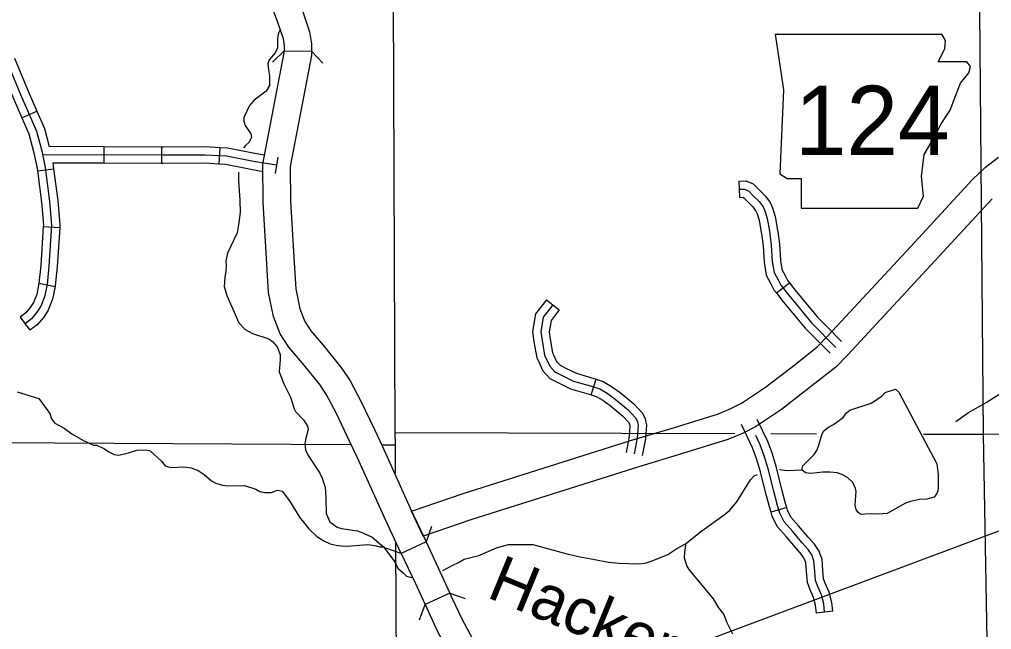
# Model space of a CAD drawing. Extents: x 1373862 to 1376999, y 1168398 to 1170455.
# Drawn here: x 1374862.3 to 1375039.9, y 1168964.7 to 1169076.3 of the extents above; entities that cross this region are included whole.
import ezdxf

# ---------------------------------------------------------------- set-up
doc = ezdxf.new("R2010")
doc.units = 0
for name, color, linetype in [('Level 10', 7, 'Continuous'), ('Level 21', 7, 'Continuous'), ('Level 32', 7, 'Continuous'), ('Level 35', 7, 'Continuous'), ('Level 37', 7, 'Continuous'), ('Level 4', 7, 'Continuous'), ('Level 45', 7, 'Continuous'), ('Level 5', 7, 'Continuous'), ('R_Draft', 7, 'Continuous')]:
    doc.layers.add(name, color=color, linetype=linetype)

msp = doc.modelspace()

# ---------------------------------------------------------------- linework, layer by layer
at = {"layer": 'Level 10'}
for p, q in [((1374910.63, 1169070.56), (1374915.63, 1169070.48)), ((1374936.55, 1168980.77), (1374932.03, 1168978.64)), ((1374940.91, 1168971.43), (1374936.37, 1168969.34))]:
    msp.add_line(p, q, dxfattribs=at)
for points in [[(1374912.68, 1169081.32), (1374914.09, 1169077.49), (1374915.29, 1169074.03), (1374915.65, 1169071.86), (1374915.63, 1169070.48)], [(1374907.99, 1169079.58), (1374909.39, 1169075.8), (1374910.43, 1169072.79), (1374910.65, 1169071.49), (1374910.63, 1169070.56)], [(1374932.03, 1168978.64), (1374929.18, 1168984.7), (1374924.04, 1168996.12), (1374922.59, 1168999.18), (1374920.12, 1169004.39), (1374918.39, 1169007.66), (1374917.16, 1169009.53), (1374913.92, 1169013.53), (1374911.5, 1169016.36), (1374909.93, 1169018.81), (1374908.7, 1169021.97), (1374907.79, 1169026.38), (1374907.46, 1169031.55), (1374906.79, 1169042.88), (1374906.71, 1169049.86), (1374910.63, 1169070.2), (1374910.63, 1169070.56)], [(1374915.63, 1169070.48), (1374915.62, 1169069.69), (1374911.71, 1169049.41), (1374911.79, 1169043.06), (1374912.46, 1169031.86), (1374912.76, 1169027.05), (1374913.51, 1169023.39), (1374914.41, 1169021.09), (1374915.53, 1169019.35), (1374917.77, 1169016.73), (1374921.19, 1169012.49), (1374922.7, 1169010.22), (1374924.59, 1169006.63), (1374927.11, 1169001.32), (1374928.58, 1168998.22), (1374933.72, 1168986.79), (1374936.55, 1168980.77)], [(1374936.04, 1168981.85), (1374933.89, 1168986.39), (1374943.36, 1168989.64), (1374973.92, 1168999.29), (1374981.94, 1169001.71), (1374989.99, 1169004.22), (1374992.37, 1169005.2), (1374994.19, 1169006.14), (1374998.57, 1169009.06), (1375003.98, 1169013.22), (1375008.03, 1169016.43), (1375009.97, 1169018.43), (1375025.11, 1169034.78), (1375036.38, 1169047.03), (1375038.77, 1169049.32), (1375041.11, 1169051.12)], [(1375039.95, 1169043.53), (1375028.78, 1169031.39), (1375013.6, 1169014.99), (1375011.4, 1169012.72), (1375007.06, 1169009.28), (1375001.48, 1169004.99), (1374996.73, 1169001.82), (1374994.46, 1169000.65), (1374991.68, 1168999.51), (1374983.4, 1168996.93), (1374975.4, 1168994.51), (1374944.92, 1168984.89), (1374936.04, 1168981.85)], [(1374936.55, 1168980.77), (1374939.08, 1168975.39), (1374940.91, 1168971.43)], [(1374932.03, 1168978.64), (1374934.55, 1168973.27), (1374936.37, 1168969.34)], [(1374955.73, 1168901.87), (1374955.94, 1168903.35), (1374956.37, 1168911.6), (1374956.65, 1168918.43), (1374957.12, 1168927.38), (1374957.6, 1168939.05), (1374957.42, 1168941.38), (1374956.94, 1168943.33), (1374956.4, 1168944.81), (1374955.5, 1168946.53), (1374954.49, 1168948.17), (1374951.51, 1168952.53), (1374947.64, 1168958.19), (1374943.07, 1168966.74), (1374940.91, 1168971.43)], [(1374936.37, 1168969.34), (1374938.59, 1168964.52), (1374943.36, 1168955.59), (1374947.39, 1168949.71), (1374950.29, 1168945.46), (1374951.15, 1168944.06), (1374951.82, 1168942.77), (1374952.15, 1168941.88), (1374952.47, 1168940.59), (1374952.6, 1168938.96), (1374952.13, 1168927.62), (1374951.65, 1168918.66), (1374951.38, 1168911.83), (1374950.96, 1168903.84), (1374950.78, 1168902.59)]]:
    msp.add_lwpolyline(points, dxfattribs=at)
at = {"layer": 'Level 21'}
for p, q in [((1375000.34, 1169073.61), (1375001.87, 1169063.46)), ((1375031.47, 1169072.43), (1375030.77, 1169073.6)), ((1375031.3, 1169070.91), (1375031.47, 1169072.43)), ((1375030.12, 1169068.54), (1375031.3, 1169070.91)), ((1375035.36, 1169068.54), (1375030.12, 1169068.54)), ((1375036.04, 1169067.69), (1375035.36, 1169068.54)), ((1375035.7, 1169066.51), (1375036.04, 1169067.69)), ((1375034.18, 1169064.65), (1375035.7, 1169066.51)), ((1375001.87, 1169063.46), (1375001.19, 1169048.07)), ((1375033.33, 1169062.45), (1375034.18, 1169064.65)), ((1375032.32, 1169059.74), (1375033.33, 1169062.45)), ((1375030.63, 1169057.2), (1375032.32, 1169059.74)), ((1375029.44, 1169054.84), (1375030.63, 1169057.2)), ((1375027.58, 1169051.62), (1375029.44, 1169054.84)), ((1375027.07, 1169047.56), (1375027.58, 1169051.62)), ((1375001.19, 1169048.07), (1375002.54, 1169047.22)), ((1375027.41, 1169044.01), (1375027.07, 1169047.56)), ((1375002.54, 1169047.22), (1375005.08, 1169047.22)), ((1375005.08, 1169047.22), (1375005.08, 1169041.81)), ((1375026.4, 1169041.81), (1375027.41, 1169044.01)), ((1375005.08, 1169041.81), (1375026.4, 1169041.81))]:
    msp.add_line(p, q, dxfattribs=at)
msp.add_lwpolyline([(1375000.34, 1169073.61), (1375030.77, 1169073.6)], dxfattribs=at)
at = {"layer": 'Level 32'}
for p, q in [((1374862.7, 1169058.31), (1374865.46, 1169059.51)), ((1374877.69, 1169053), (1374877.68, 1169050)), ((1374888.25, 1169052.97), (1374888.24, 1169049.97)), ((1374898.88, 1169052.85), (1374898.72, 1169049.86)), ((1374909.45, 1169051.11), (1374908.97, 1169048.15)), ((1374865.55, 1169048.62), (1374868.52, 1169049.01)), ((1374866.63, 1169038.42), (1374869.62, 1169038.23)), ((1374865.84, 1169028.09), (1374868.78, 1169027.5))]:
    msp.add_line(p, q, dxfattribs=at)
for points in [[(1374858.41, 1169072.35), (1374862.49, 1169062.57), (1374865.4, 1169055.87), (1374866.38, 1169052.27), (1374866.98, 1169049.26), (1374867.79, 1169043.03), (1374868.15, 1169038.71), (1374867.67, 1169031.19), (1374867.31, 1169027.83), (1374866.87, 1169025.58), (1374866.15, 1169023.86), (1374865.47, 1169022.75), (1374864.49, 1169021.53), (1374863.3, 1169020.67)], [(1374861.35, 1169069.21), (1374863.87, 1169063.16), (1374865.46, 1169059.51)], [(1374858.58, 1169068.05), (1374861.11, 1169061.98), (1374862.7, 1169058.31)], [(1374862.7, 1169058.31), (1374863.98, 1169055.37), (1374864.92, 1169051.93), (1374865.5, 1169049.02), (1374865.55, 1169048.62)], [(1374865.46, 1169059.51), (1374866.82, 1169056.37), (1374867.73, 1169053.04)], [(1374877.69, 1169053), (1374867.73, 1169053.04)], [(1374888.25, 1169052.97), (1374877.69, 1169053)], [(1374898.88, 1169052.85), (1374896.25, 1169053), (1374888.52, 1169052.97), (1374888.25, 1169052.97)], [(1374907.02, 1169051.5), (1374905.28, 1169051.78), (1374900.3, 1169052.78), (1374898.88, 1169052.85)], [(1374909.21, 1169049.63), (1374905.02, 1169050.3), (1374900.11, 1169051.29), (1374896.21, 1169051.5), (1374888.52, 1169051.47), (1374866.53, 1169051.54)], [(1374877.68, 1169050), (1374868.35, 1169050.04)], [(1374868.35, 1169050.04), (1374868.46, 1169049.51), (1374868.52, 1169049.01)], [(1374888.24, 1169049.97), (1374877.68, 1169050)], [(1374898.72, 1169049.86), (1374896.17, 1169050), (1374888.52, 1169049.97), (1374888.24, 1169049.97)], [(1374906.72, 1169048.43), (1374899.92, 1169049.79), (1374898.72, 1169049.86)], [(1374865.55, 1169048.62), (1374866.3, 1169042.87), (1374866.64, 1169038.7), (1374866.63, 1169038.42)], [(1374868.52, 1169049.01), (1374869.28, 1169043.19), (1374869.65, 1169038.73), (1374869.62, 1169038.23)], [(1374866.63, 1169038.42), (1374866.18, 1169031.32), (1374865.83, 1169028.06), (1374865.84, 1169028.09)], [(1374869.62, 1169038.23), (1374869.17, 1169031.07), (1374868.8, 1169027.6), (1374868.78, 1169027.5)], [(1374865.84, 1169028.09), (1374865.43, 1169026.02), (1374864.81, 1169024.54), (1374864.24, 1169023.62), (1374863.44, 1169022.63), (1374862.42, 1169021.88), (1374864.18, 1169019.46)], [(1374868.78, 1169027.5), (1374868.31, 1169025.14), (1374867.49, 1169023.17), (1374866.7, 1169021.88), (1374865.53, 1169020.44), (1374864.18, 1169019.46)]]:
    msp.add_lwpolyline(points, dxfattribs=at)
at = {"layer": 'Level 35'}
for points in [[(1374909.88, 1169074.38), (1374909.6, 1169073.81), (1374909.44, 1169072.85), (1374909.42, 1169071.12), (1374909.01, 1169070.22), (1374907.89, 1169068.89), (1374907.67, 1169068.17), (1374907.75, 1169067.09), (1374907.98, 1169066), (1374907.94, 1169064.21), (1374907.35, 1169063.19), (1374905.18, 1169061.57), (1374904.29, 1169060.56)], [(1374904.29, 1169060.56), (1374903.28, 1169058.4), (1374903.27, 1169057.7), (1374903.5, 1169056.92), (1374904.57, 1169055.38), (1374904.66, 1169054.72), (1374904.17, 1169053.81), (1374903.56, 1169053.26), (1374903.21, 1169052.84)], [(1374902.29, 1169048.38), (1374902.26, 1169046.82), (1374902.51, 1169043.26), (1374902.57, 1169041.02), (1374902.32, 1169038.75), (1374902.02, 1169037.26), (1374900.3, 1169033.59), (1374900, 1169032.12), (1374900.06, 1169031.26), (1374899.97, 1169030.25)], [(1374899.97, 1169030.25), (1374899.77, 1169029.13), (1374899.65, 1169027.46), (1374900.16, 1169025.83), (1374902.33, 1169020.83), (1374903.51, 1169019.59), (1374904.82, 1169018.86), (1374907.84, 1169017.89), (1374908.52, 1169017.4), (1374909.36, 1169016.47), (1374909.88, 1169015.03), (1374909.89, 1169014.05), (1374909.73, 1169011.86), (1374910.56, 1169009.67), (1374911.76, 1169007.26), (1374912.43, 1169005.09), (1374912.73, 1169004.63), (1374914.16, 1169003.07), (1374914.9, 1169001.92), (1374915, 1169001.32), (1374914.57, 1168999.77), (1374914.38, 1168998.75), (1374914.52, 1168997.59), (1374915.04, 1168996.59), (1374917.12, 1168993.34), (1374917.56, 1168992.42), (1374918.12, 1168990.77), (1374918.27, 1168988.86), (1374918.28, 1168985.98), (1374919, 1168984.47), (1374920.29, 1168983.46), (1374921.08, 1168983.2), (1374921.98, 1168983.13), (1374924, 1168982.78), (1374924.99, 1168982.43), (1374926.68, 1168981.62), (1374928.8, 1168979.85), (1374930.82, 1168977.11), (1374931.41, 1168975.95), (1374932.35, 1168975.1), (1374932.98, 1168974.52), (1374933.94, 1168974.25)], [(1375001.1, 1168993.99), (1375002.51, 1168993.84), (1375005.23, 1168993.96), (1375005.38, 1168994.69), (1375007.47, 1168996.76), (1375007.92, 1168997.49), (1375008.26, 1168998.3), (1375008.91, 1169000.51), (1375009.22, 1169001.06), (1375010.05, 1169001.77), (1375010.96, 1169002.25), (1375012.76, 1169003.5), (1375013.39, 1169004.39), (1375014, 1169004.86), (1375017.88, 1169006.14), (1375019.84, 1169007.45), (1375020.41, 1169008.06), (1375022.32, 1169008.73), (1375022.93, 1169008.18), (1375029.86, 1168995.02), (1375030.09, 1168993.1), (1375030.11, 1168990.63), (1375030.04, 1168990.11), (1375029.83, 1168989.55), (1375029.4, 1168988.98), (1375028.04, 1168988.58), (1375026.68, 1168988.5), (1375025.03, 1168988.17), (1375024.16, 1168987.84), (1375020.81, 1168985.98), (1375019.19, 1168985.86), (1375017.37, 1168985.91), (1375016.09, 1168985.79), (1375015.71, 1168985.94), (1375015.49, 1168986.16), (1375015.14, 1168986.7), (1375014.97, 1168987.46), (1375015.11, 1168990.02), (1375015.02, 1168990.56), (1375014.52, 1168991.62), (1375013.53, 1168992.55), (1375012.52, 1168993.09), (1375011.64, 1168993.4), (1375010.34, 1168993.54), (1375009.02, 1168993.52), (1375006.86, 1168993.25), (1375005.86, 1168993.43), (1375005.23, 1168993.96)], [(1374861.87, 1169008.23), (1374865.82, 1169007.02), (1374867.8, 1169004.27), (1374868.14, 1169003.27), (1374868.75, 1169002.48), (1374870.46, 1169001.56), (1374871.86, 1169000.52), (1374873.85, 1168999.35), (1374875.81, 1168998.48), (1374876.39, 1168998.45), (1374877.82, 1168997.81), (1374878.62, 1168997.22), (1374879.55, 1168996.77), (1374880.45, 1168996.66), (1374882.17, 1168997.03), (1374883.74, 1168997.54)], [(1375033.32, 1169002.79), (1375035.66, 1169004.41), (1375038.87, 1169006.24), (1375042.04, 1169008.25)], [(1374883.74, 1168997.54), (1374885.32, 1168997.62), (1374886.16, 1168997.43), (1374888.21, 1168995.52), (1374888.92, 1168994.71), (1374889.46, 1168994.48), (1374890.14, 1168994.39), (1374892.34, 1168994.48), (1374893.66, 1168994.34), (1374894.93, 1168993.82), (1374896, 1168993.07), (1374897.38, 1168991.91), (1374898.14, 1168991.54), (1374899.39, 1168991.12), (1374900.37, 1168991), (1374903.37, 1168991.08), (1374905.43, 1168990.43), (1374906.18, 1168989.96), (1374907.12, 1168989.8), (1374908.3, 1168989.81), (1374909.42, 1168990.23), (1374910.28, 1168990.05), (1374911.6, 1168988.26), (1374913.43, 1168985.32), (1374915.14, 1168983.16), (1374916.6, 1168981.78), (1374917.89, 1168980.96), (1374919.06, 1168980.44), (1374920.16, 1168980.15), (1374921.13, 1168980.03), (1374922.15, 1168979.98), (1374925.94, 1168980.3), (1374927.18, 1168980.14), (1374928.14, 1168979.86), (1374928.8, 1168979.85)], [(1374993.33, 1168988.09), (1374995.8, 1168992.13), (1374996.51, 1168992.83), (1374997.08, 1168993.11)], [(1374967.36, 1168977.53), (1374969.87, 1168977.07), (1374971.81, 1168976.9), (1374975.28, 1168976.75), (1374976.61, 1168976.87), (1374977.67, 1168977.28), (1374979.37, 1168977.91), (1374980.74, 1168978.44), (1374982.38, 1168979.56), (1374983.93, 1168980.41), (1374986.91, 1168982.82), (1374991.02, 1168985.73), (1374992.01, 1168986.52), (1374993.33, 1168988.09)], [(1374939.6, 1168975.53), (1374941.42, 1168976.51), (1374942.51, 1168976.99), (1374943.5, 1168977.63), (1374946.17, 1168978.26), (1374949.43, 1168979.66), (1374951.6, 1168980.32), (1374956.09, 1168980.28), (1374962.5, 1168978.54), (1374964.69, 1168978.02), (1374967.36, 1168977.53)], [(1374983.93, 1168980.41), (1374983.9, 1168979.61), (1374983.75, 1168978.98), (1374983.73, 1168977.84), (1374984.17, 1168976.36), (1374984.56, 1168975.75), (1374985.39, 1168974.72), (1374988.99, 1168970.38), (1374989.98, 1168968.69), (1374990.97, 1168967.47), (1374991.44, 1168966.13), (1374992.53, 1168963.94)]]:
    msp.add_lwpolyline(points, dxfattribs=at)
at = {"layer": 'Level 37'}
for points in [[(1374908.48, 1169068.47), (1374910.63, 1169070.56)], [(1374915.63, 1169070.48), (1374917.72, 1169068.33)], [(1374937.57, 1168983.59), (1374936.55, 1168980.77)], [(1374932.03, 1168978.64), (1374929.21, 1168979.65)], [(1374940.91, 1168971.43), (1374943.72, 1168970.4)], [(1374935.33, 1168966.52), (1374936.37, 1168969.34)]]:
    msp.add_lwpolyline(points, dxfattribs=at)
at = {"layer": 'Level 4'}
for points in [[(1374930.57, 1169080.13), (1374930.88, 1169000.77), (1374930.9, 1168998.52), (1374930.92, 1168993.33)], [(1374931, 1168980.63), (1374931.12, 1168958.04)]]:
    msp.add_lwpolyline(points, dxfattribs=at)
at = {"layer": 'Level 45'}
for p, q in [((1374993.88, 1169043.77), (1374993.78, 1169046.76)), ((1375000.55, 1169026.32), (1375002.93, 1169028.15)), ((1374958.54, 1169025.04), (1374960.9, 1169023.19)), ((1374966.69, 1169007.68), (1374967.61, 1169010.54)), ((1375002.44, 1168987.09), (1374999.58, 1168986.2)), ((1375010.86, 1168968.1), (1375007.88, 1168967.77))]:
    msp.add_line(p, q, dxfattribs=at)
for points in [[(1374993.78, 1169046.76), (1374994.96, 1169046.81), (1374996.29, 1169046.24), (1374997.46, 1169045.07), (1374998.56, 1169043.97), (1374999.41, 1169042.8), (1374999.87, 1169041.84), (1375000.34, 1169040.27), (1375000.77, 1169037.8), (1375000.81, 1169037.52)], [(1374993.83, 1169045.27), (1374994.68, 1169045.29), (1374995.44, 1169044.97), (1374996.4, 1169044.01), (1374997.42, 1169042.99), (1374998.12, 1169042.03), (1374998.47, 1169041.3), (1374998.88, 1169039.93), (1374999.28, 1169037.57), (1374999.63, 1169035.06), (1374999.81, 1169032.07), (1375000.12, 1169030.05), (1375000.89, 1169028.67), (1375001.39, 1169027.7), (1375002.75, 1169025.92), (1375006.94, 1169020.85), (1375011.42, 1169016.33)], [(1374993.88, 1169043.77), (1374994.4, 1169043.78), (1374994.58, 1169043.71), (1374995.34, 1169042.95), (1374996.27, 1169042.01), (1374996.82, 1169041.26), (1374997.06, 1169040.76), (1374997.41, 1169039.59), (1374997.8, 1169037.33), (1374997.83, 1169037.1)], [(1374997.83, 1169037.1), (1374998.14, 1169034.91), (1374998.32, 1169031.92), (1374998.68, 1169029.56), (1374999.57, 1169027.96), (1375000.11, 1169026.89), (1375000.55, 1169026.32)], [(1375000.81, 1169037.52), (1375001.13, 1169035.21), (1375001.3, 1169032.23), (1375001.56, 1169030.55), (1375002.22, 1169029.38), (1375002.66, 1169028.5), (1375002.93, 1169028.15)], [(1375002.93, 1169028.15), (1375003.93, 1169026.86), (1375008.05, 1169021.86), (1375009.64, 1169020.26)], [(1375000.55, 1169026.32), (1375001.58, 1169024.99), (1375005.82, 1169019.84), (1375007.51, 1169018.14)], [(1374958.54, 1169025.04), (1374956.54, 1169022.5), (1374956, 1169019.22), (1374956.26, 1169017.38), (1374956.78, 1169014.44), (1374957.13, 1169013.68)], [(1374959.72, 1169024.12), (1374957.96, 1169021.88), (1374957.52, 1169019.2), (1374957.74, 1169017.62), (1374958.22, 1169014.89), (1374959.15, 1169012.92), (1374960.11, 1169011.86), (1374961.52, 1169011.12), (1374963.49, 1169010.19), (1374966.79, 1169009.23), (1374968.28, 1169008.74), (1374969.64, 1169007.95), (1374971.09, 1169006.9), (1374973.46, 1169004.92), (1374974.82, 1169003.47), (1374975.17, 1169002.77), (1374975.31, 1169002.07), (1374975.13, 1168999.82), (1374974.57, 1168996.87)], [(1374960.9, 1169023.19), (1374959.38, 1169021.26), (1374959.04, 1169019.18), (1374959.22, 1169017.85), (1374959.67, 1169015.35), (1374959.85, 1169014.95)], [(1375009.64, 1169020.26), (1375012.48, 1169017.39)], [(1375007.51, 1169018.14), (1375010.35, 1169015.28)], [(1374957.13, 1169013.68), (1374957.88, 1169012.07), (1374959.18, 1169010.66), (1374960.85, 1169009.77), (1374962.96, 1169008.79), (1374966.34, 1169007.79), (1374966.69, 1169007.68)], [(1374959.85, 1169014.95), (1374960.41, 1169013.76), (1374961.04, 1169013.07), (1374962.19, 1169012.46), (1374964.02, 1169011.6), (1374967.23, 1169010.66), (1374967.61, 1169010.54)], [(1374967.61, 1169010.54), (1374968.89, 1169010.12), (1374970.46, 1169009.21), (1374972.01, 1169008.08), (1374974.49, 1169006.01), (1374976.07, 1169004.34), (1374976.61, 1169003.25), (1374976.67, 1169002.9)], [(1374966.69, 1169007.68), (1374967.66, 1169007.37), (1374968.82, 1169006.69), (1374970.17, 1169005.71), (1374972.43, 1169003.83), (1374973.58, 1169002.6), (1374973.74, 1169002.29), (1374973.73, 1169002.35)], [(1374999.64, 1168997.35), (1374998.97, 1168999.13), (1374997.04, 1169003.18)], [(1374973.73, 1169002.35), (1374973.8, 1169001.98), (1374973.64, 1169000.02), (1374973.1, 1168997.15)], [(1374976.67, 1169002.9), (1374976.82, 1169002.15), (1374976.62, 1168999.63), (1374976.05, 1168996.6)], [(1374996.83, 1168996.3), (1374996.21, 1168997.96), (1374994.16, 1169002.25)], [(1375009.37, 1168967.94), (1375009.2, 1168969.45), (1375008.79, 1168971.11), (1375008.1, 1168972.62), (1375007.69, 1168973.69), (1375007.57, 1168975.45), (1375007.42, 1168977.29), (1375007.01, 1168978.41), (1375006.35, 1168979.41), (1375005.23, 1168980.66), (1375003.48, 1168982.76), (1375001.96, 1168984.46), (1375001.2, 1168986.03), (1375000.77, 1168987.41), (1375000.1, 1168990), (1374999.1, 1168993.98), (1374998.35, 1168996.52), (1374997.59, 1168998.54), (1374996.78, 1169000.25)], [(1374999.58, 1168986.2), (1374999.33, 1168987), (1374998.65, 1168989.63), (1374997.66, 1168993.58), (1374996.93, 1168996.04), (1374996.83, 1168996.3)], [(1375002.44, 1168987.09), (1375002.22, 1168987.82), (1375001.56, 1168990.37), (1375000.55, 1168994.38), (1374999.77, 1168996.99), (1374999.64, 1168997.35)], [(1375008.51, 1168978.66), (1375008.35, 1168979.09), (1375007.54, 1168980.33), (1375006.36, 1168981.64), (1375004.62, 1168983.74), (1375003.22, 1168985.31), (1375002.6, 1168986.58), (1375002.44, 1168987.09)], [(1375005.7, 1168977.63), (1375005.66, 1168977.73), (1375005.16, 1168978.49), (1375004.09, 1168979.68), (1375002.34, 1168981.78), (1375000.7, 1168983.62), (1374999.8, 1168985.47), (1374999.58, 1168986.2)], [(1375010.86, 1168968.1), (1375010.68, 1168969.72), (1375010.21, 1168971.6), (1375009.49, 1168973.2), (1375009.17, 1168974.02), (1375009.06, 1168975.56), (1375008.9, 1168977.62), (1375008.51, 1168978.66)], [(1375007.88, 1168967.77), (1375007.72, 1168969.18), (1375007.36, 1168970.61), (1375006.72, 1168972.04), (1375006.21, 1168973.36), (1375006.07, 1168975.34), (1375005.94, 1168976.97), (1375005.7, 1168977.63)]]:
    msp.add_lwpolyline(points, dxfattribs=at)
at = {"layer": 'Level 5'}
for points in [[(1375037.4, 1169106.13), (1375038.34, 1169000.46)], [(1375038.34, 1169000.46), (1375143.05, 1169001.54)], [(1374930.88, 1169000.77), (1374992.99, 1169000.59)], [(1374999.55, 1169000.58), (1375007.89, 1169000.55)], [(1375027.46, 1169000.5), (1375038.34, 1169000.46)], [(1375038.34, 1169000.46), (1375039.8, 1168918.35)], [(1374825.44, 1168999.12), (1374922.66, 1168998.57)], [(1374928.39, 1168998.53), (1374930.9, 1168998.52)]]:
    msp.add_lwpolyline(points, dxfattribs=at)
at = {"layer": 'R_Draft'}
msp.add_line((1375430.86, 1169128.62), (1374608.59, 1168820.86), dxfattribs=at)

# ---------------------------------------------------------------- texts
at = {"layer": 'Level 21'}
msp.add_text('124', height=12.672, dxfattribs=at).set_placement((1375003.93, 1169051.5))
at = {"layer": 'Level 35'}
msp.add_text('Hackers', height=8.448, rotation=337.6494, dxfattribs=at).set_placement((1374947.39, 1168970.74))

doc.saveas('drawing.dxf')
